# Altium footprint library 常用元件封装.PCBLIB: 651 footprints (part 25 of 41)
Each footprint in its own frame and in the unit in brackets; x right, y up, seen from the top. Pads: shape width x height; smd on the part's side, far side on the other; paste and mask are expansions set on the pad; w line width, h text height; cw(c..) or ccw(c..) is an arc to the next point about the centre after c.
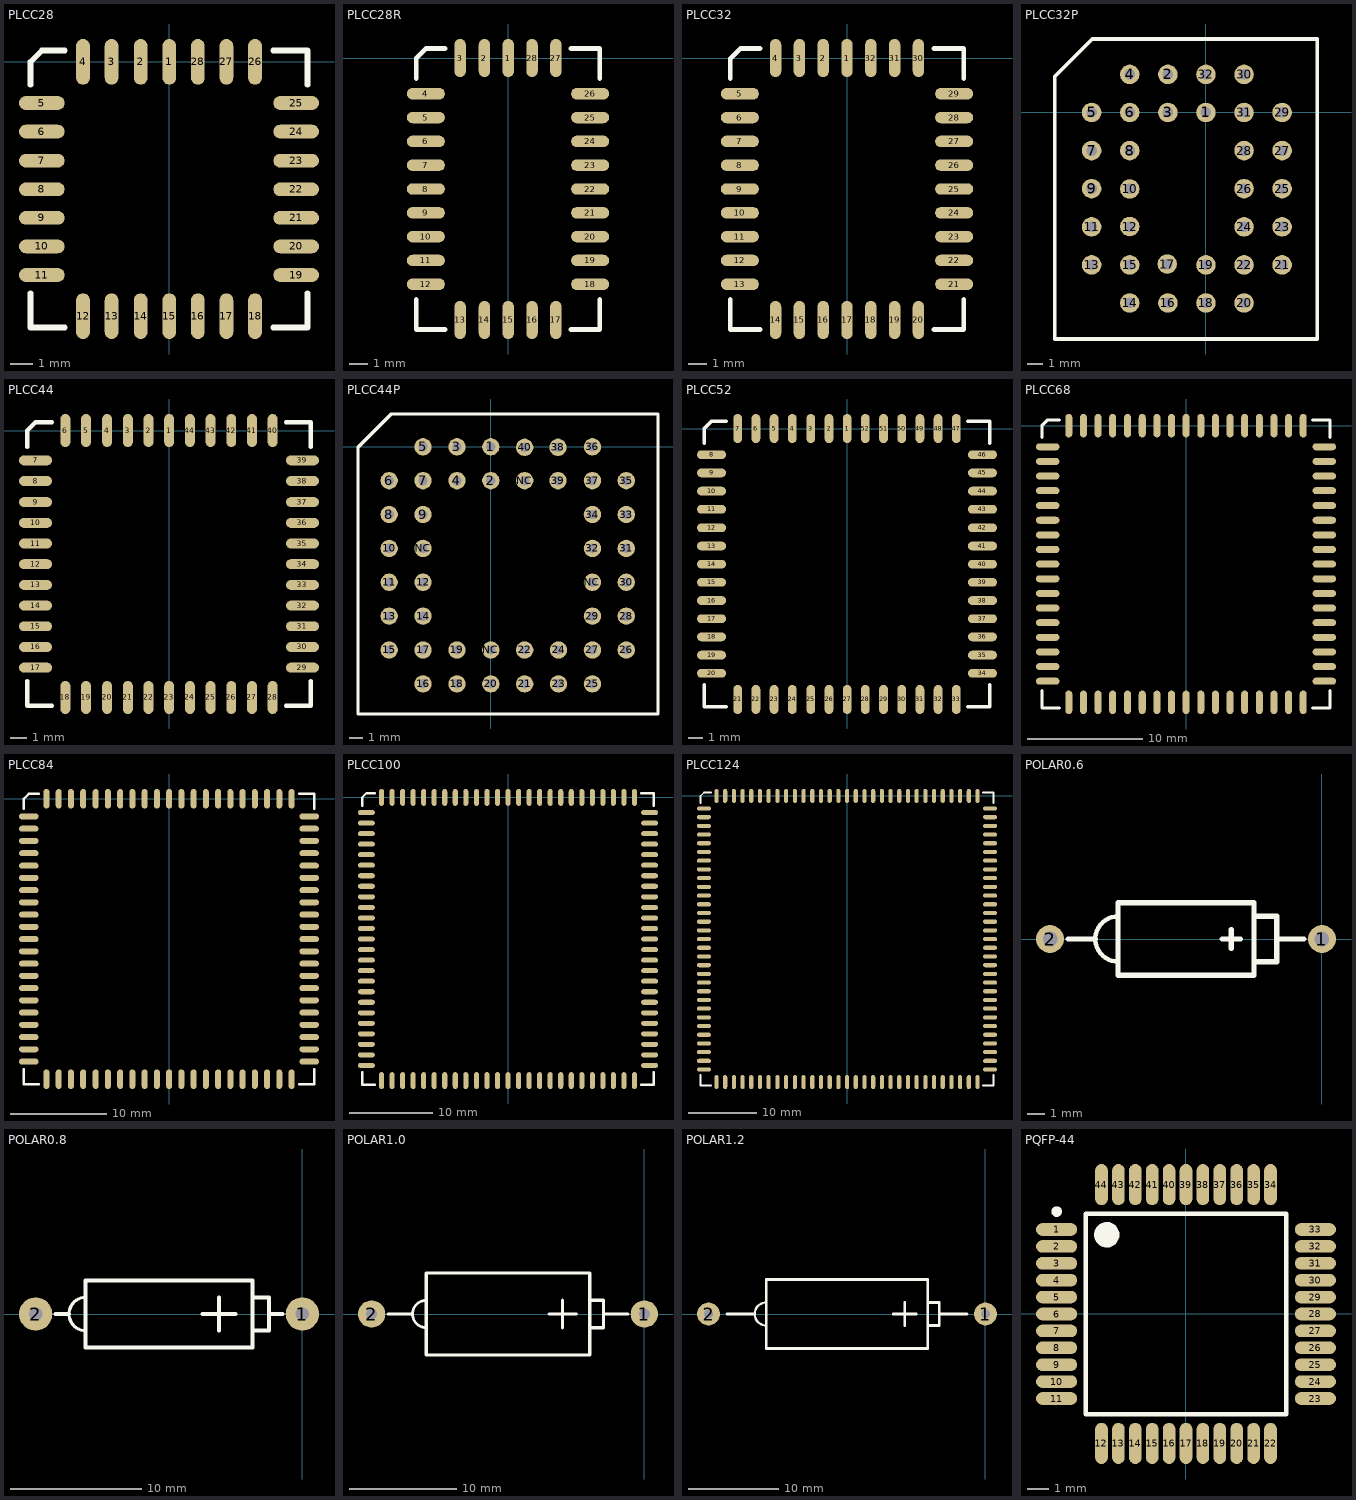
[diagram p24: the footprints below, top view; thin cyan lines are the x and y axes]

## PLCC28 [mil]
pads (28):
  oval 24x80 smd: 1(0,0) 2(-50,0) 3(-101,0) 4(-151,0) 12(-151,-445) 13(-101,-445) 14(-50,-445) 15(0,-445) 16(50,-445) 17(100,-445) 18(150,-445) 26(150,0) 27(100,0) 28(50,0)
  oval 80x24 smd: 5(-223,-72) 6(-223,-122) 7(-223,-173) 8(-223,-223) 9(-223,-273) 10(-223,-323) 11(-223,-373) 19(222,-373) 20(222,-323) 21(222,-273) 22(222,-223) 23(222,-173) 24(222,-122) 25(222,-72)
TopOverlay:
  lines w10: -243,-405 -243,-465 -183,-465 ; -243,-40 -243,0 -223,20 -183,20 ; 182,-465 242,-465 242,-405 ; 182,20 242,20 242,-40

## PLCC28R [mil]
pads (28):
  oval 24x80 smd: 1(0,0) 2(-50,0) 3(-101,0) 13(-101,-550) 14(-50,-550) 15(0,-550) 16(50,-550) 17(100,-550) 27(100,0) 28(50,0)
  oval 80x24 smd: 4(-173,-75) 5(-173,-125) 6(-173,-175) 7(-173,-225) 8(-173,-275) 9(-173,-325) 10(-173,-375) 11(-173,-425) 12(-173,-475) 18(172,-475) 19(172,-425) 20(172,-375) 21(172,-325) 22(172,-275) 23(172,-225) 24(172,-175) 25(172,-125) 26(172,-75)
TopOverlay:
  lines w10: -193,-507 -193,-570 -133,-570 ; -193,-43 -193,0 -173,20 -133,20 ; 132,-570 192,-570 192,-507 ; 132,20 192,20 192,-43

## PLCC32 [mil]
pads (32):
  oval 24x80 smd: 1(0,0) 2(-50,0) 3(-100,0) 4(-150,0) 14(-150,-550) 15(-100,-550) 16(-50,-550) 17(0,-550) 18(50,-550) 19(100,-550) 20(150,-550) 30(150,0) 31(100,0) 32(50,0)
  oval 80x24 smd: 5(-225,-75) 6(-225,-125) 7(-225,-175) 8(-225,-225) 9(-225,-275) 10(-225,-325) 11(-225,-375) 12(-225,-425) 13(-225,-475) 21(225,-475) 22(225,-425) 23(225,-375) 24(225,-325) 25(225,-275) 26(225,-225) 27(225,-175) 28(225,-125) 29(225,-75)
TopOverlay:
  lines w10: -245,-507 -245,-570 -182,-570 ; -245,-43 -245,-1 -224,20 -182,20 ; 182,-570 245,-570 245,-507 ; 182,20 245,20 245,-43

## PLCC32P [mm]
pads (32):
  round 1.3 hole 0.7: 1(0,0) 2(-2.54,2.54) 3(-2.54,0) 4(-5.08,2.54) 5(-7.62,0) 6(-5.08,0) 7(-7.62,-2.54) 8(-5.08,-2.54) 9(-7.62,-5.08) 10(-5.08,-5.1) 11(-7.62,-7.62) 12(-5.08,-7.6) 13(-7.62,-10.16) 14(-5.08,-12.7) 15(-5.08,-10.16) 16(-2.54,-12.7) 17(-2.58,-10.1) 18(0,-12.7) 19(0,-10.16) 20(2.54,-12.7) 21(5.08,-10.16) 22(2.54,-10.16) 23(5.08,-7.62) 24(2.54,-7.62) 25(5.08,-5.08) 26(2.54,-5.08) 27(5.08,-2.54) 28(2.54,-2.54) 29(5.08,0) 30(2.54,2.54) 31(2.54,0) 32(0,2.54)
TopOverlay:
  lines w0.254: -10.08,-15.1 7.42,-15.1 7.42,4.9 -5.08,4.9 -7.58,4.9 -10.08,2.4 -10.08,-0.1 -10.08,-15.1

## PLCC44 [mil]
pads (44):
  oval 24x80 smd: 1(0,0) 2(-50,0) 3(-100,0) 4(-150,0) 5(-201,0) 6(-251,0) 18(-251,-645) 19(-201,-645) 20(-150,-645) 21(-100,-645) 22(-50,-645) 23(0,-645) 24(50,-645) 25(100,-645) 26(150,-645) 27(200,-645) 28(250,-645) 40(250,0) 41(200,0) 42(150,0) 43(100,0) 44(50,0)
  oval 80x24 smd: 7(-323,-72) 8(-323,-122) 9(-323,-173) 10(-323,-223) 11(-323,-273) 12(-323,-323) 13(-323,-373) 14(-323,-423) 15(-323,-473) 16(-323,-523) 17(-323,-573) 29(322,-573) 30(322,-523) 31(322,-473) 32(322,-423) 33(322,-373) 34(322,-323) 35(322,-273) 36(322,-223) 37(322,-173) 38(322,-122) 39(322,-72)
TopOverlay:
  lines w10: -343,-605 -343,-665 -283,-665 ; -343,-40 -343,0 -323,20 -283,20 ; 282,-665 342,-665 342,-605 ; 282,20 342,20 342,-40

## PLCC44P [mm]
pads (44):
  round 1.3 hole 0.7: 1(0,0) 2(0,-2.54) 3(-2.54,0) 4(-2.54,-2.54) 5(-5.08,0) 6(-7.62,-2.54) 7(-5.08,-2.54) 8(-7.62,-5.08) 9(-5.08,-5.08) 10(-7.62,-7.62) 11(-7.62,-10.16) 12(-5.08,-10.16) 13(-7.62,-12.7) 14(-5.08,-12.7) 15(-7.62,-15.24) 16(-5.08,-17.78) 17(-5.08,-15.24) 18(-2.54,-17.78) 19(-2.54,-15.24) 20(0,-17.78) 21(2.54,-17.78) 22(2.54,-15.24) 23(5.08,-17.78) 24(5.08,-15.24) 25(7.62,-17.78) 26(10.16,-15.24) 27(7.62,-15.24) 28(10.16,-12.7) 29(7.62,-12.7) 30(10.16,-10.16) 31(10.16,-7.62) 32(7.62,-7.62) 33(10.16,-5.08) 34(7.62,-5.08) 35(10.16,-2.54) 36(7.62,0) 37(7.62,-2.54) 38(5.04,-0.04) 39(5.04,-2.54) 40(2.54,-0.04) NC(-5.08,-7.62) NC(0,-15.24) NC(2.54,-2.54) NC(7.62,-10.16)
TopOverlay:
  lines w0.254: -9.96,-20.04 -9.96,-2.54 -9.96,-0.04 -7.46,2.46 -4.96,2.46 12.54,2.46 12.54,-20.04 -9.96,-20.04

## PLCC52 [mil]
pads (52):
  oval 24x80 smd: 1(0,0) 2(-50,0) 3(-100,0) 4(-151,0) 5(-201,0) 6(-251,0) 7(-301,0) 21(-301,-745) 22(-251,-745) 23(-201,-745) 24(-151,-745) 25(-100,-745) 26(-50,-745) 27(0,-745) 28(50,-745) 29(100,-745) 30(150,-745) 31(200,-745) 32(250,-745) 33(300,-745) 47(300,0) 48(250,0) 49(200,0) 50(150,0) 51(100,0) 52(50,0)
  oval 80x24 smd: 8(-373,-72) 9(-373,-122) 10(-373,-172) 11(-373,-222) 12(-373,-273) 13(-373,-323) 14(-373,-373) 15(-373,-423) 16(-373,-473) 17(-373,-523) 18(-373,-573) 19(-373,-623) 20(-373,-673) 34(372,-673) 35(372,-623) 36(372,-573) 37(372,-523) 38(372,-473) 39(372,-423) 40(372,-373) 41(372,-323) 42(372,-273) 43(372,-222) 44(372,-172) 45(372,-122) 46(372,-72)
TopOverlay:
  lines w10: -393,-705 -393,-765 -333,-765 ; -393,-40 -393,0 -373,20 -333,20 ; 332,-765 392,-765 392,-705 ; 332,20 392,20 392,-40

## PLCC68 [mil]
pads (68):
  oval 24x80 smd: 1(0,0) 2(-50,0) 3(-100,0) 4(-150,0) 5(-200,0) 6(-251,0) 7(-301,0) 8(-351,0) 9(-401,0) 27(-401,-945) 28(-351,-945) 29(-301,-945) 30(-251,-945) 31(-200,-945) 32(-150,-945) 33(-100,-945) 34(-50,-945) 35(0,-945) 36(50,-945) 37(100,-945) 38(150,-945) 39(200,-945) 40(250,-945) 41(300,-945) 42(350,-945) 43(400,-945) 61(400,0) 62(350,0) 63(300,0) 64(250,0) 65(200,0) 66(150,0) 67(100,0) 68(50,0)
  oval 80x24 smd: 10(-473,-72) 11(-473,-122) 12(-473,-172) 13(-473,-222) 14(-473,-273) 15(-473,-323) 16(-473,-373) 17(-473,-423) 18(-473,-473) 19(-473,-523) 20(-473,-573) 21(-473,-623) 22(-473,-673) 23(-473,-723) 24(-473,-773) 25(-473,-823) 26(-473,-873) 44(472,-873) 45(472,-823) 46(472,-773) 47(472,-723) 48(472,-673) 49(472,-623) 50(472,-573) 51(472,-523) 52(472,-473) 53(472,-423) 54(472,-373) 55(472,-323) 56(472,-273) 57(472,-222) 58(472,-172) 59(472,-122) 60(472,-72)
TopOverlay:
  lines w10: -493,-905 -493,-965 -433,-965 ; -493,-40 -493,0 -473,20 -433,20 ; 432,-965 492,-965 492,-905 ; 432,20 492,20 492,-40

## PLCC84 [mil]
pads (84):
  oval 24x80 smd: 1(0,0) 2(-50,0) 3(-100,0) 4(-150,0) 5(-200,0) 6(-250,0) 7(-300,0) 8(-351,0) 9(-401,0) 10(-451,0) 11(-501,0) 33(-501,-1145) 34(-451,-1145) 35(-401,-1145) 36(-351,-1145) 37(-300,-1145) 38(-250,-1145) 39(-200,-1145) 40(-150,-1145) 41(-100,-1145) 42(-50,-1145) 43(0,-1145) 44(50,-1145) 45(100,-1145) 46(150,-1145) 47(200,-1145) 48(250,-1145) 49(300,-1145) 50(350,-1145) 51(400,-1145) 52(450,-1145) 53(500,-1145) 75(500,0) 76(450,0) 77(400,0) 78(350,0) 79(300,0) 80(250,0) 81(200,0) 82(150,0) 83(100,0) 84(50,0)
  oval 80x24 smd: 12(-573,-72) 13(-573,-122) 14(-573,-172) 15(-573,-222) 16(-573,-273) 17(-573,-323) 18(-573,-373) 19(-573,-423) 20(-573,-473) 21(-573,-523) 22(-573,-573) 23(-573,-623) 24(-573,-673) 25(-573,-723) 26(-573,-773) 27(-573,-823) 28(-573,-873) 29(-573,-923) 30(-573,-973) 31(-573,-1023) 32(-573,-1073) 54(572,-1073) 55(572,-1023) 56(572,-973) 57(572,-923) 58(572,-873) 59(572,-823) 60(572,-773) 61(572,-723) 62(572,-673) 63(572,-623) 64(572,-573) 65(572,-523) 66(572,-473) 67(572,-423) 68(572,-373) 69(572,-323) 70(572,-273) 71(572,-222) 72(572,-172) 73(572,-122) 74(572,-72)
TopOverlay:
  lines w10: -593,-1105 -593,-1165 -533,-1165 ; -593,-40 -593,0 -573,20 -533,20 ; 532,-1165 592,-1165 592,-1105 ; 532,20 592,20 592,-40

## PLCC100 [mil]
pads (100):
  oval 24x80 smd: 1(0,0) 2(-50,0) 3(-100,0) 4(-150,0) 5(-201,0) 6(-251,0) 7(-301,0) 8(-351,0) 9(-401,0) 10(-451,0) 11(-501,0) 12(-551,0) 13(-601,0) 39(-601,-1345) 40(-551,-1345) 41(-501,-1345) 42(-451,-1345) 43(-401,-1345) 44(-351,-1345) 45(-301,-1345) 46(-251,-1345) 47(-201,-1345) 48(-150,-1345) 49(-100,-1345) 50(-50,-1345) 51(0,-1345) 52(50,-1345) 53(100,-1345) 54(150,-1345) 55(200,-1345) 56(250,-1345) 57(300,-1345) 58(350,-1345) 59(400,-1345) 60(450,-1345) 61(500,-1345) 62(550,-1345) 63(600,-1345) 89(600,0) 90(550,0) 91(500,0) 92(450,0) 93(400,0) 94(350,0) 95(300,0) 96(250,0) 97(200,0) 98(150,0) 99(100,0) 100(50,0)
  oval 80x24 smd: 14(-673,-72) 15(-673,-122) 16(-673,-172) 17(-673,-222) 18(-673,-272) 19(-673,-322) 20(-673,-372) 21(-673,-422) 22(-673,-472) 23(-673,-523) 24(-673,-573) 25(-673,-623) 26(-673,-673) 27(-673,-723) 28(-673,-773) 29(-673,-823) 30(-673,-873) 31(-673,-923) 32(-673,-973) 33(-673,-1023) 34(-673,-1073) 35(-673,-1123) 36(-673,-1173) 37(-673,-1223) 38(-673,-1273) 64(672,-1273) 65(672,-1223) 66(672,-1173) 67(672,-1123) 68(672,-1073) 69(672,-1023) 70(672,-973) 71(672,-923) 72(672,-873) 73(672,-823) 74(672,-773) 75(672,-723) 76(672,-673) 77(672,-623) 78(672,-573) 79(672,-523) 80(672,-472) 81(672,-422) 82(672,-372) 83(672,-322) 84(672,-272) 85(672,-222) 86(672,-172) 87(672,-122) 88(672,-72)
TopOverlay:
  lines w10: -693,-1305 -693,-1365 -633,-1365 ; -693,-40 -693,0 -673,20 -633,20 ; 632,-1365 692,-1365 692,-1305 ; 632,20 692,20 692,-40

## PLCC124 [mil]
pads (124):
  oval 24x80 smd: 1(0,0) 2(-50,0) 3(-100,0) 4(-150,0) 5(-200,0) 6(-250,0) 7(-300,0) 8(-351,0) 9(-401,0) 10(-451,0) 11(-501,0) 12(-551,0) 13(-601,0) 14(-651,0) 15(-701,0) 16(-751,0) 48(-751,-1645) 49(-701,-1645) 50(-651,-1645) 51(-601,-1645) 52(-551,-1645) 53(-501,-1645) 54(-451,-1645) 55(-401,-1645) 56(-351,-1645) 57(-300,-1645) 58(-250,-1645) 59(-200,-1645) 60(-150,-1645) 61(-100,-1645) 62(-50,-1645) 63(0,-1645) 64(50,-1645) 65(100,-1645) 66(150,-1645) 67(200,-1645) 68(250,-1645) 69(300,-1645) 70(350,-1645) 71(400,-1645) 72(450,-1645) 73(500,-1645) 74(550,-1645) 75(600,-1645) 76(650,-1645) 77(700,-1645) 78(750,-1645) 110(750,0) 111(700,0) 112(650,0) 113(600,0) 114(550,0) 115(500,0) 116(450,0) 117(400,0) 118(350,0) 119(300,0) 120(250,0) 121(200,0) 122(150,0) 123(100,0) 124(50,0)
  oval 80x24 smd: 17(-823,-72) 18(-823,-122) 19(-823,-172) 20(-823,-222) 21(-823,-272) 22(-823,-322) 23(-823,-372) 24(-823,-422) 25(-823,-472) 26(-823,-523) 27(-823,-573) 28(-823,-623) 29(-823,-673) 30(-823,-723) 31(-823,-773) 32(-823,-823) 33(-823,-873) 34(-823,-923) 35(-823,-973) 36(-823,-1023) 37(-823,-1073) 38(-823,-1123) 39(-823,-1173) 40(-823,-1223) 41(-823,-1273) 42(-823,-1323) 43(-823,-1373) 44(-823,-1423) 45(-823,-1473) 46(-823,-1523) 47(-823,-1573) 79(822,-1573) 80(822,-1523) 81(822,-1473) 82(822,-1423) 83(822,-1373) 84(822,-1323) 85(822,-1273) 86(822,-1223) 87(822,-1173) 88(822,-1123) 89(822,-1073) 90(822,-1023) 91(822,-973) 92(822,-923) 93(822,-873) 94(822,-823) 95(822,-773) 96(822,-723) 97(822,-673) 98(822,-623) 99(822,-573) 100(822,-523) 101(822,-472) 102(822,-422) 103(822,-372) 104(822,-322) 105(822,-272) 106(822,-222) 107(822,-172) 108(822,-122) 109(822,-72)
TopOverlay:
  lines w10: -843,-1605 -843,-1665 -783,-1665 ; -843,-40 -843,0 -823,20 -783,20 ; 782,-1665 842,-1665 842,-1605 ; 782,20 842,20 842,-40

## POLAR0.6 [mil]
pads (2):
  round 62 hole 32: 1(0,0) 2(-600,0)
TopOverlay:
  lines w10: -450,-50 cw(c-450,0) -450,50
  lines w12: -560,0 -500,0 ; -220,0 -180,0 ; -200,-20 -200,20 ; -150,-50 -100,-50 -100,50 -150,50 ; -100,0 -40,0 ; -450,-80 -150,-80 -150,80 -450,80 -450,-80

## POLAR0.8 [mil]
pads (2):
  round 100 hole 40: 1(0,0) 2(-800,0)
TopOverlay:
  lines w10: -650,-50 cw(c-650,0) -650,50
  lines w12: -740,0 -700,0 ; -300,0 -200,0 ; -250,-50 -250,50 ; -150,-50 -100,-50 -100,50 -150,50 ; -100,0 -60,0 ; -650,-100 -150,-100 -150,100 -650,100 -650,-100

## POLAR1.0 [mil]
pads (2):
  round 100 hole 40: 1(0,0) 2(-1000,0)
TopOverlay:
  lines w10: -800,-50 cw(c-800,0) -800,50
  lines w12: -940,0 -850,0 ; -350,0 -250,0 ; -300,-50 -300,50 ; -200,-50 -150,-50 -150,50 -200,50 ; -150,0 -60,0 ; -800,-150 -800,150 -200,150 -200,-150 -800,-150

## POLAR1.2 [mil]
pads (2):
  round 100 hole 40: 1(0,0) 2(-1200,0)
TopOverlay:
  lines w10: -950,-50 cw(c-950,0) -950,50
  lines w12: -1120,0 -1000,0 ; -400,0 -300,0 ; -350,-50 -350,50 ; -250,-50 -200,-50 -200,50 -250,50 ; -200,0 -80,0 ; -950,-150 -950,150 -250,150 -250,-150 -950,-150

## PQFP-44 [mm] "QFP, 44-Leads, Body 13.4x13.4mm (max), Pitch 0.80mm"
height 2.7
pads (44):
  oval 1.95x0.6 smd: 1(-6.125,4) 2(-6.125,3.2) 3(-6.125,2.4) 4(-6.125,1.6) 5(-6.125,0.8) 6(-6.125,0) 7(-6.125,-0.8) 8(-6.125,-1.6) 9(-6.125,-2.4) 10(-6.125,-3.2) 11(-6.125,-4) 23(6.125,-4) 24(6.125,-3.2) 25(6.125,-2.4) 26(6.125,-1.6) 27(6.125,-0.8) 28(6.125,0) 29(6.125,0.8) 30(6.125,1.6) 31(6.125,2.4) 32(6.125,3.2) 33(6.125,4)
  oval 0.6x1.95 smd: 12(-4,-6.125) 13(-3.2,-6.125) 14(-2.4,-6.125) 15(-1.6,-6.125) 16(-0.8,-6.125) 17(0,-6.125) 18(0.8,-6.125) 19(1.6,-6.125) 20(2.4,-6.125) 21(3.2,-6.125) 22(4,-6.125) 34(4,6.125) 35(3.2,6.125) 36(2.4,6.125) 37(1.6,6.125) 38(0.8,6.125) 39(0,6.125) 40(-0.8,6.125) 41(-1.6,6.125) 42(-2.4,6.125) 43(-3.2,6.125) 44(-4,6.125)
TopOverlay:
  circle w0.25: c-6.125,4.85 r0.125
  circle w0.6: c-3.75,3.75 r0.3
  lines w0.2: -4.75,-4.75 -4.75,4.75 4.75,4.75 4.75,-4.75 -4.75,-4.75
